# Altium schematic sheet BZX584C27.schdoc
size 127 x 101 mm
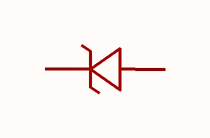
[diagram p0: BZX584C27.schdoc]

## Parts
D?  bzx584c27  [SOD-523_L1.2-W0.8-LS1.6-RD]  (value not drawn)

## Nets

Not connected (* = marked no-connect by the designer): D? 1(K) 2(A)

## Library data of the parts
D? = bzx584c27: 二极管配置:1个独立式;稳压值(标称值):27V;稳压值(范围值):25.1V~28.9V;耗散功率(Pd):150mW;; Manufacturer: CJ(江苏长电/长晶); AddInBom: yes; ModelId: 8f56a03db567494d8f4c9d12aa52a741; ModelName: SOD-523_L1.2-W0.8-H0.7-LS1.6; ModelTransform: 62.992,31.496,0,180,0,0,0,0,0; Diode Configuration: 1个独立式; Zener Voltage(Nom): 27V; Reverse Leakage Current (Ir): 100nA; Pd - Power Dissipation: 150mW; Impedance(Zzt): 80Ω; Impedance(Zzk): 300Ω; Operating Junction Temperature Range: -55℃~+150℃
